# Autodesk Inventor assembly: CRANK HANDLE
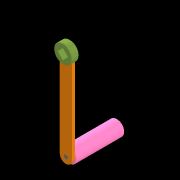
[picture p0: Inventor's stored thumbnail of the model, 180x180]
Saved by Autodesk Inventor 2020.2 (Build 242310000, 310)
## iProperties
Manager: ASSEMBLY
Company: 20
Created: 2020-10
Part Number: CRANK HANDLE
Document SubType Name: Assembly
Designer: Apardo
Cost Center: 1
Description: CRANK HANDLE
Engineer: STEEL METAL / WOOD
Stock Number: 2
Project: PLATE ROLLING MACHINE
Engr Approved By: D. JAEGER
Author: Apardo
Revision Number: 1.0
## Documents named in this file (5)
- C:\Users\Apardo\Documents\Proyectos\Dietrich\Proyecto 1\PLATE ROLLING MACHINE\CRANK HANDLE.iam
- C:\Users\Apardo\Documents\Proyectos\Dietrich\Proyecto 1\PLATE ROLLING MACHINE\crank handle1.ipt
- C:\Users\Apardo\Documents\Proyectos\Dietrich\Proyecto 1\PLATE ROLLING MACHINE\crank handle2.ipt
- C:\Users\Apardo\Documents\Proyectos\Dietrich\Proyecto 1\PLATE ROLLING MACHINE\crank handle3.ipt
- C:\Users\Apardo\Documents\Inventor\Content Center Files\R2020\en-US\ANSI B18.3.1M(4)\ANSI B18.3.1M - M8x1,25 x 70(4).ipt
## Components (4 placed, 4 different names)
1. crank handle1:1 — Mate:1, Insert:1
2. crank handle2:1 — Mate:1, Insert:1, Insert:2, Insert:3
3. crank handle3:1 — Insert:3
4. Drilled Forged Hexagon Socket Head Cap Screw - 2 Holes - Metric M8x1,25 x 70:1 — Insert:2
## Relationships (4: Insert 3, Mate 1)
- Mate:1: crank handle1:1 ↔ crank handle2:1
- Insert:1: crank handle1:1 ↔ crank handle2:1
- Insert:2: crank handle2:1 ↔ Drilled Forged Hexagon Socket Head Cap Screw - 2 Holes - Metric M8x1,25 x 70:1
- Insert:3: crank handle2:1 ↔ crank handle3:1
